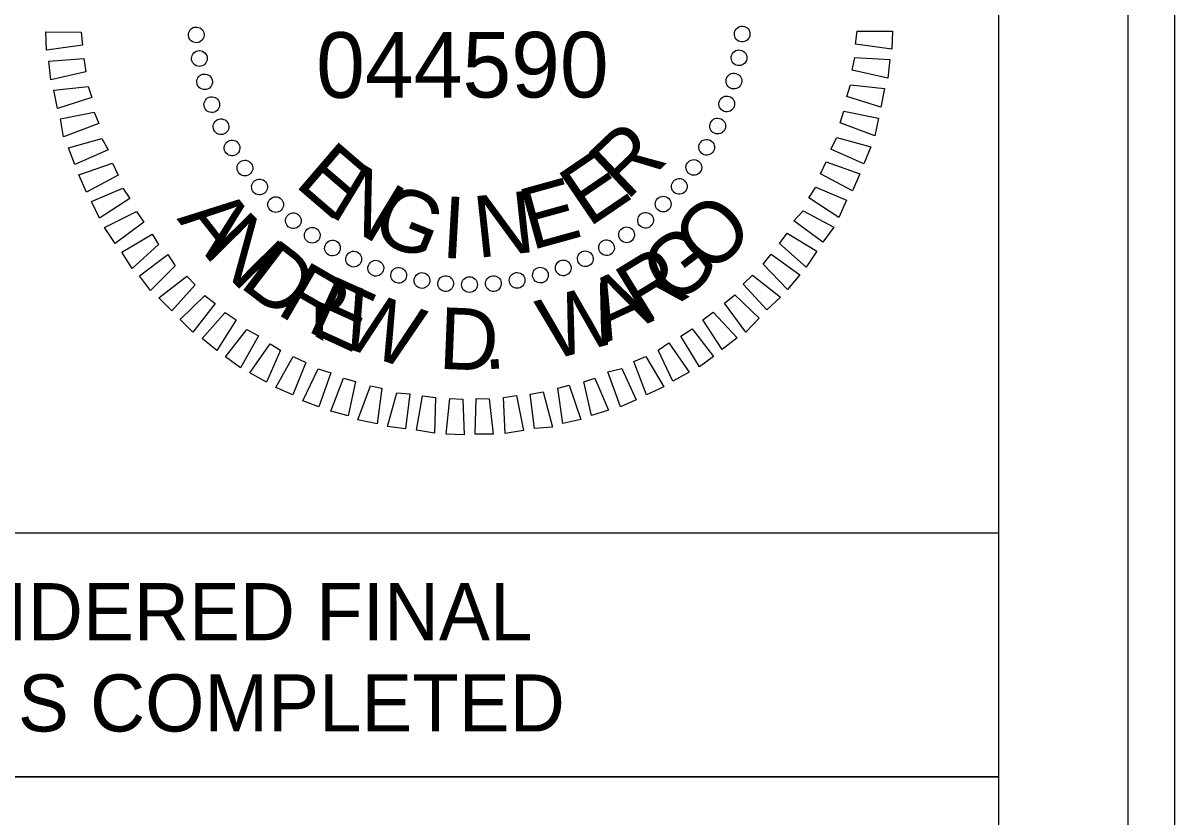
# Model space of a CAD drawing. Extents: x 2320980 to 2456309, y 595047 to 606177.
# Drawn here: x 2456023.3 to 2456045.51, y 596044.59 to 596059.89 of the extents above; entities that cross this region are included whole.
import ezdxf

# ---------------------------------------------------------------- set-up
doc = ezdxf.new("R2010")
doc.units = 0
for name, color, linetype in [('Default', 7, 'Continuous'), ('Prop Dimension', 7, 'Continuous'), ('Sheet Plan CELL', 7, 'Continuous'), ('Sheet Plot Border Inside CELL', 7, 'Continuous'), ('Sheet Plot Border Outside CELL', 7, 'Continuous'), ('Sheet Sticker Exception Certification CELL', 7, 'Continuous')]:
    doc.layers.add(name, color=color, linetype=linetype)

msp = doc.modelspace()

# ---------------------------------------------------------------- linework, layer by layer
at = {"layer": 'Default'}
for p, q in [((2456026.634, 596059.653), (2456026.634, 596059.653)), ((2456026.634, 596059.653), (2456026.634, 596059.653)), ((2456037.167, 596059.673), (2456037.167, 596059.673)), ((2456037.167, 596059.673), (2456037.167, 596059.673)), ((2456026.705, 596059.212), (2456026.705, 596059.212)), ((2456026.705, 596059.212), (2456026.705, 596059.212)), ((2456037.102, 596059.218), (2456037.102, 596059.218)), ((2456037.102, 596059.218), (2456037.102, 596059.218)), ((2456026.799, 596058.75), (2456026.799, 596058.75)), ((2456026.799, 596058.75), (2456026.799, 596058.75)), ((2456037.015, 596058.774), (2456037.015, 596058.774)), ((2456037.015, 596058.774), (2456037.015, 596058.774)), ((2456026.933, 596058.31), (2456026.933, 596058.31)), ((2456026.933, 596058.31), (2456026.933, 596058.31)), ((2456036.876, 596058.329), (2456036.876, 596058.329)), ((2456036.876, 596058.329), (2456036.876, 596058.329)), ((2456027.11, 596057.882), (2456027.11, 596057.882)), ((2456027.11, 596057.882), (2456027.11, 596057.882)), ((2456036.695, 596057.905), (2456036.695, 596057.905)), ((2456036.695, 596057.905), (2456036.695, 596057.905)), ((2456027.328, 596057.486), (2456027.328, 596057.486)), ((2456027.328, 596057.486), (2456027.328, 596057.486)), ((2456036.492, 596057.49), (2456036.492, 596057.49)), ((2456036.492, 596057.49), (2456036.492, 596057.49)), ((2456027.577, 596057.09), (2456027.577, 596057.09)), ((2456027.577, 596057.09), (2456027.577, 596057.09)), ((2456036.236, 596057.106), (2456036.236, 596057.106)), ((2456036.236, 596057.106), (2456036.236, 596057.106)), ((2456027.848, 596056.727), (2456027.848, 596056.727)), ((2456027.848, 596056.727), (2456027.848, 596056.727)), ((2456035.958, 596056.721), (2456035.958, 596056.721)), ((2456035.958, 596056.721), (2456035.958, 596056.721)), ((2456028.17, 596056.385), (2456028.17, 596056.385)), ((2456028.17, 596056.385), (2456028.17, 596056.385)), ((2456035.649, 596056.399), (2456035.649, 596056.399)), ((2456035.649, 596056.399), (2456035.649, 596056.399)), ((2456028.492, 596056.075), (2456028.492, 596056.075)), ((2456028.492, 596056.075), (2456028.492, 596056.075)), ((2456035.297, 596056.077), (2456035.297, 596056.077)), ((2456035.297, 596056.077), (2456035.297, 596056.077)), ((2456028.876, 596055.798), (2456028.876, 596055.798)), ((2456028.876, 596055.798), (2456028.876, 596055.798)), ((2456034.943, 596055.807), (2456034.943, 596055.807)), ((2456034.943, 596055.807), (2456034.943, 596055.807)), ((2456029.261, 596055.541), (2456029.261, 596055.541)), ((2456029.261, 596055.541), (2456029.261, 596055.541)), ((2456034.548, 596055.557), (2456034.548, 596055.557)), ((2456034.548, 596055.557), (2456034.548, 596055.557)), ((2456029.675, 596055.329), (2456029.675, 596055.329)), ((2456029.675, 596055.329), (2456029.675, 596055.329)), ((2456033.713, 596055.162), (2456033.713, 596055.162)), ((2456033.713, 596055.162), (2456033.713, 596055.162)), ((2456034.141, 596055.339), (2456034.141, 596055.339)), ((2456034.141, 596055.339), (2456034.141, 596055.339)), ((2456030.089, 596055.147), (2456030.089, 596055.147)), ((2456030.089, 596055.147), (2456030.089, 596055.147)), ((2456030.545, 596055.019), (2456030.545, 596055.019)), ((2456030.545, 596055.019), (2456030.545, 596055.019)), ((2456030.989, 596054.932), (2456030.989, 596054.932)), ((2456030.989, 596054.932), (2456030.989, 596054.932)), ((2456032.822, 596054.935), (2456032.822, 596054.935)), ((2456032.822, 596054.935), (2456032.822, 596054.935)), ((2456033.283, 596055.028), (2456033.283, 596055.028)), ((2456033.283, 596055.028), (2456033.283, 596055.028)), ((2456031.443, 596054.867), (2456031.443, 596054.867)), ((2456031.443, 596054.867), (2456031.443, 596054.867)), ((2456031.907, 596054.844), (2456031.907, 596054.844)), ((2456031.907, 596054.844), (2456031.907, 596054.844)), ((2456032.37, 596054.863), (2456032.37, 596054.863)), ((2456032.37, 596054.863), (2456032.37, 596054.863))]:
    msp.add_line(p, q, dxfattribs=at)
for points in [[(2456024.446, 596059.464), (2456023.753, 596059.367), (2456023.736, 596059.725), (2456024.421, 596059.717)], [(2456039.377, 596059.735), (2456040.062, 596059.738), (2456040.048, 596059.39), (2456039.351, 596059.482)], [(2456024.509, 596058.949), (2456023.837, 596058.799), (2456023.799, 596059.157), (2456024.472, 596059.212)], [(2456039.334, 596059.229), (2456040.009, 596059.189), (2456039.974, 596058.831), (2456039.286, 596058.986)], [(2456024.624, 596058.457), (2456023.964, 596058.244), (2456023.894, 596058.601), (2456024.556, 596058.666)], [(2456039.25, 596058.701), (2456039.904, 596058.629), (2456039.837, 596058.269), (2456039.18, 596058.478)], [(2456024.759, 596057.953), (2456024.08, 596057.698), (2456024.02, 596058.044), (2456024.671, 596058.173)], [(2456039.123, 596058.193), (2456039.789, 596058.057), (2456039.721, 596057.719), (2456039.053, 596057.97)], [(2456024.938, 596057.451), (2456024.3, 596057.165), (2456024.178, 596057.49), (2456024.817, 596057.67)], [(2456038.985, 596057.685), (2456039.641, 596057.507), (2456039.51, 596057.178), (2456038.873, 596057.461)], [(2456025.136, 596056.959), (2456024.521, 596056.632), (2456024.378, 596056.966), (2456025.027, 596057.189)], [(2456038.782, 596057.217), (2456039.43, 596056.988), (2456039.288, 596056.658), (2456038.671, 596056.983)], [(2456025.355, 596056.511), (2456024.773, 596056.131), (2456024.619, 596056.455), (2456025.225, 596056.709)], [(2456038.581, 596056.729), (2456039.176, 596056.477), (2456039.024, 596056.147), (2456038.448, 596056.526)], [(2456038.337, 596056.271), (2456038.933, 596055.956), (2456038.718, 596055.668), (2456038.162, 596056.078)], [(2456025.627, 596056.053), (2456025.077, 596055.642), (2456024.871, 596055.954), (2456025.486, 596056.261)], [(2456025.91, 596055.626), (2456025.402, 596055.163), (2456025.206, 596055.475), (2456025.79, 596055.824)], [(2456038.029, 596055.844), (2456038.604, 596055.497), (2456038.4, 596055.188), (2456037.885, 596055.641)], [(2456026.233, 596055.211), (2456025.757, 596054.738), (2456025.542, 596055.019), (2456026.092, 596055.429)], [(2456037.721, 596055.438), (2456038.276, 596055.038), (2456038.039, 596054.759), (2456037.566, 596055.246)], [(2456026.619, 596054.849), (2456026.165, 596054.346), (2456025.918, 596054.594), (2456026.458, 596055.015)], [(2456037.36, 596055.031), (2456037.905, 596054.61), (2456037.636, 596054.362), (2456037.184, 596054.859)], [(2456027.005, 596054.488), (2456026.573, 596053.932), (2456026.327, 596054.18), (2456026.802, 596054.642)], [(2456037.02, 596054.656), (2456037.491, 596054.202), (2456037.233, 596053.933), (2456036.822, 596054.494)], [(2456027.411, 596054.169), (2456027.033, 596053.583), (2456026.754, 596053.809), (2456027.198, 596054.313)], [(2456036.604, 596054.322), (2456037.067, 596053.825), (2456036.776, 596053.598), (2456036.407, 596054.17)], [(2456027.838, 596053.861), (2456027.492, 596053.244), (2456027.204, 596053.459), (2456027.615, 596053.984)], [(2456036.2, 596053.998), (2456036.61, 596053.468), (2456036.34, 596053.263), (2456035.981, 596053.857)], [(2456028.265, 596053.585), (2456027.992, 596052.968), (2456027.673, 596053.152), (2456028.063, 596053.708)], [(2456035.752, 596053.726), (2456036.141, 596053.165), (2456035.829, 596052.99), (2456035.544, 596053.585)], [(2456028.754, 596053.352), (2456028.503, 596052.726), (2456028.173, 596052.867), (2456028.51, 596053.463)], [(2456035.304, 596053.465), (2456035.652, 596052.881), (2456035.317, 596052.728), (2456035.074, 596053.366)], [(2456029.232, 596053.15), (2456029.002, 596052.493), (2456028.694, 596052.613), (2456028.988, 596053.23)], [(2456034.845, 596053.235), (2456035.119, 596052.629), (2456034.817, 596052.497), (2456034.572, 596053.167)], [(2456029.709, 596052.98), (2456029.564, 596052.324), (2456029.235, 596052.413), (2456029.476, 596053.049)], [(2456034.322, 596053.046), (2456034.586, 596052.43), (2456034.261, 596052.329), (2456034.112, 596052.979)], [(2456030.217, 596052.853), (2456030.125, 596052.167), (2456029.754, 596052.243), (2456029.995, 596052.901)], [(2456030.756, 596052.747), (2456030.674, 596052.071), (2456030.326, 596052.118), (2456030.503, 596052.764)], [(2456032.811, 596052.712), (2456032.95, 596052.041), (2456032.593, 596051.981), (2456032.559, 596052.676)], [(2456033.325, 596052.785), (2456033.507, 596052.104), (2456033.16, 596052.076), (2456033.074, 596052.738)], [(2456033.829, 596052.91), (2456034.052, 596052.251), (2456033.706, 596052.171), (2456033.609, 596052.854)], [(2456031.253, 596052.672), (2456031.234, 596051.987), (2456030.885, 596052.044), (2456030.999, 596052.709)], [(2456031.78, 596052.64), (2456031.804, 596051.956), (2456031.456, 596051.97), (2456031.527, 596052.656)], [(2456032.285, 596052.649), (2456032.361, 596051.967), (2456032.014, 596051.97), (2456032.033, 596052.656)]]:
    msp.add_lwpolyline(points, close=True, dxfattribs=at)
for centre, major_axis in [((2456026.638, 596059.665), (-0.151, -0.013)), ((2456037.163, 596059.68), (0.151, -0.013)), ((2456037.103, 596059.223), (0.149, -0.026)), ((2456026.699, 596059.209), (-0.149, -0.027)), ((2456037.004, 596058.773), (0.147, -0.039)), ((2456026.799, 596058.759), (-0.146, -0.039)), ((2456026.938, 596058.319), (-0.142, -0.052)), ((2456036.866, 596058.333), (0.143, -0.052)), ((2456027.115, 596057.894), (-0.137, -0.064)), ((2456036.691, 596057.907), (0.138, -0.064)), ((2456027.329, 596057.485), (-0.131, -0.076)), ((2456036.478, 596057.498), (0.131, -0.076)), ((2456027.577, 596057.097), (-0.124, -0.087)), ((2456036.231, 596057.109), (0.124, -0.087)), ((2456027.858, 596056.732), (-0.116, -0.098)), ((2456035.951, 596056.743), (0.116, -0.097)), ((2456028.17, 596056.393), (-0.107, -0.107)), ((2456035.64, 596056.403), (0.107, -0.107)), ((2456028.51, 596056.082), (-0.097, -0.116)), ((2456035.301, 596056.091), (0.098, -0.116)), ((2456028.876, 596055.802), (-0.087, -0.124)), ((2456034.936, 596055.81), (0.087, -0.124)), ((2456029.265, 596055.555), (-0.076, -0.131)), ((2456034.548, 596055.562), (0.076, -0.131)), ((2456029.674, 596055.342), (-0.064, -0.138)), ((2456034.139, 596055.349), (0.064, -0.137)), ((2456030.1, 596055.167), (-0.052, -0.143)), ((2456030.54, 596055.029), (-0.039, -0.147)), ((2456033.274, 596055.033), (0.039, -0.146)), ((2456033.714, 596055.172), (0.052, -0.142)), ((2456030.99, 596054.93), (-0.026, -0.149)), ((2456031.447, 596054.87), (-0.013, -0.151)), ((2456031.907, 596054.851), (0, -0.152)), ((2456032.368, 596054.871), (0.013, -0.151)), ((2456032.824, 596054.932), (0.027, -0.149))]:
    msp.add_ellipse(centre, major_axis=major_axis, ratio=0.999708, dxfattribs=at)
at = {"layer": 'Prop Dimension'}
msp.add_lwpolyline([(2455998.637, 596045.366), (2456042.107, 596045.366), (2456042.107, 596041.09), (2455998.637, 596041.09)], close=True, dxfattribs=at)
at = {"layer": 'Sheet Plan CELL'}
for points in [[(2455742.104, 595870.076), (2455742.099, 596080.071), (2456002.097, 596080.079), (2456002.099, 596050.066), (2456042.107, 596050.064), (2456042.107, 595870.076)], [(2456042.112, 596080.076), (2455742.104, 596080.076), (2455742.104, 595870.076), (2456042.107, 595870.076)], [(2456022.107, 596072.564), (2456042.104, 596072.566), (2456042.107, 596050.064), (2456022.107, 596050.061)]]:
    msp.add_lwpolyline(points, close=True, dxfattribs=at)
at = {"layer": 'Sheet Plot Border Inside CELL'}
msp.add_lwpolyline([(2455711.407, 595869.574), (2456044.604, 595869.576), (2456044.607, 596080.574), (2455711.407, 596080.574)], close=True, dxfattribs=at)
at = {"layer": 'Sheet Plot Border Outside CELL'}
msp.add_lwpolyline([(2455708.807, 595865.574), (2456045.507, 595865.574), (2456045.507, 596084.574), (2455708.807, 596084.574)], close=True, dxfattribs=at)
at = {"layer": 'Sheet Sticker Exception Certification CELL'}
for p, q in [((2456002.099, 596050.066), (2456042.107, 596050.066)), ((2456042.107, 596050.064), (2456042.107, 596045.364)), ((2456042.107, 596045.366), (2456002.099, 596045.366))]:
    msp.add_line(p, q, dxfattribs=at)

# ---------------------------------------------------------------- texts
at = {"layer": 'Default'}
for s, height, rotation, p in [('044590', 1.2638, 0.081, (2456028.951, 596058.451)), ('R', 1.188, 43.5624, (2456034.931, 596056.449)), ('E', 1.188, 319.3578, (2456028.51, 596056.771)), ('E', 1.188, 34.205, (2456034.203, 596055.94)), ('N', 1.188, 328.7149, (2456029.152, 596056.214)), ('G', 1.188, 338.0712, (2456029.962, 596055.755)), ('E', 1.188, 15.4927, (2456033.095, 596055.509)), ('A', 1.188, 308.1238, (2456026.255, 596056.117)), ('I', 1.188, 356.7822, (2456031.349, 596055.371)), ('N', 1.188, 6.1373, (2456032.055, 596055.363)), ('O', 1.188, 45.0203, (2456036.566, 596055.007)), ('N', 1.188, 314.6899, (2456026.751, 596055.497)), ('G', 1.188, 37.0537, (2456035.811, 596054.41)), ('D', 1.188, 322.6565, (2456027.443, 596054.828)), ('R', 1.188, 31.4977, (2456035.238, 596054.058)), ('R', 1.188, 329.9918, (2456028.156, 596054.302)), ('E', 1.188, 335.5478, (2456028.738, 596053.967)), ('A', 1.188, 24.9316, (2456034.522, 596053.717)), ('W', 1.188, 340.8282, (2456029.319, 596053.702)), ('W', 1.188, 15.6219, (2456033.45, 596053.377)), ('D', 1.188, 357.7142, (2456031.298, 596053.229)), ('.', 1.188, 5.0495, (2456032.184, 596053.208))]:
    msp.add_text(s, height=height, rotation=rotation, dxfattribs=at).set_placement(p)
at = {"layer": 'Sheet Sticker Exception Certification CELL'}
for s, p in [('DOCUMENT NOT CONSIDERED FINAL', (2456006.313, 596047.997)), ('UNLESS ALL SIGNATURES COMPLETED', (2456005.299, 596046.237))]:
    msp.add_text(s, height=1.1, dxfattribs=at).set_placement(p)

doc.saveas('drawing.dxf')
